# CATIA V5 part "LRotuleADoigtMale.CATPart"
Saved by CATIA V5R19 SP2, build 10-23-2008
Part number: RotuleADoigtMale
Publications: "Centre", "Doigt", "Facteur d'échelle"
Bounding box of the stored display mesh (mm): x -5 to 5, y -4.99 to 4.99, z -4.981 to 5.5
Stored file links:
  E:\Mes documents\03_Ressources pédagogiques\01_Catia\Buggy Dassault\SchemaCinematiqueFinal\LRotuleADoigtMale.CATPart
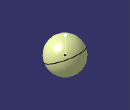
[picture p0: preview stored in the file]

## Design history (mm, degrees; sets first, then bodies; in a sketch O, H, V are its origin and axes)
Parameters
  `Facteur d'échelle` = 2
Body1 "RotuleADoigtMale" (main body)
  Point1 "Centre": (0, 0, 0)
  Circle1: type CtrRad, Start 0, End 180, Center Point1, Support xy-plane, Radius 5 {= 2.5mm*`Facteur d'échelle`}, FirstDirection (1, 0, 0)
  Revol1: Element1 Circle1, Line X axis, Angle1 180
  Line1 "AxeDoigt": type PtDir, RefPoint Point1, Direction (0, 0, 1), Start 0, End 5.5 {= 2.75mm*`Facteur d'échelle`}
  Point2 "Doigt": type OnCurve, Support Line1, Ratio 1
